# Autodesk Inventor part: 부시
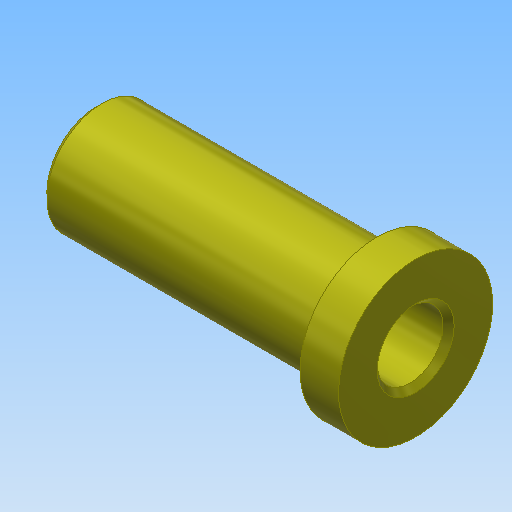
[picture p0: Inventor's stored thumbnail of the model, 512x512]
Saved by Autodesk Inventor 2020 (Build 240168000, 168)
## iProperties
Created: 2016-11
Part Number: 부시
Material: 강철, 연강
Document SubType Name: Modeling
Designer: mduedu
Density: 7.86 g/cm^3
Appearance: 노란색
Mass: 107.859 g
Surface Area: 69.5315 cm^2
Volume: 13.7225 cm^3
Author: mduedu
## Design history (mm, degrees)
sketch "스케치1"
  geometry: L1 (0, 0)-(58, 0); L2 (58, 0)-(58, 14); L3 (58, 14)-(51, 14); L4 (51, 14)-(51, 10); L5 (51, 10)-(0, 10); L6 (0, 10)-(0, 0)
  constraints: 12 end point, 3 parallel, 2 perpendicular, 1 horizontal
  dimensions: "d0" = 58 distance of L1.start L1.end; "d1" = 7 distance of L2.end L3.end; "d2" = 28 diameter of L3 L1; "d3" = 20 diameter of L5 L1
revolve "회전1" sketch "스케치1" stored, may be unused: angle "d4" = 90 deg
hole "구멍1" diameter "d7" = 12; stored, may be unused: countersink angle "d11" = 90 deg, drill point angle "d13" = 118 deg; dims "d5" = 10, "d6" = 10, "d8" = 6, "d9" = 4, "d10" = 2, "d12" = 8
chamfer "모따기1" distance "d14" = 1; stored, may be unused: second distance "d15" = 2, angle "d16" = 45 deg
node "솔리드1"
